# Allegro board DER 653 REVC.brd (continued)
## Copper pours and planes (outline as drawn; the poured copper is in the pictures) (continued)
PHASEW on TOP: 61.16,97.75 61.16,95.9 61.23,95.82 62.83,95.82 63.65,96.63 68.05,96.63 68.13,96.72 68.13,98.83 67.94,99.02 64.62,99.02 64.04,98.44 60.47,98.44 58.92,99.99 58.54,99.99 58.52,99.96 58.52,99.3 58.54,99.27 58.92,99.27 60.32,97.88 61.03,97.88
PHASEW on TOP: 58.97,99.25 53.18,99.25 53.08,99.35 53.08,103.16 51.23,105.02 48.66,105.02 48.23,105.45 48.23,109.5 48.25,109.51 48.25,110.09 49,110.84 70.23,110.84 70.74,110.33 70.74,105.84 70.51,105.61 60.48,105.61 58.97,104.1
PHASEW on BOTTOM: 48.39,99.5 48.39,113.29 48.92,113.83 80.1,113.83 81.26,112.67 81.26,102.76 79.62,101.13 71.87,101.13 70.13,99.39 70.12,99.39 69.85,99.12 48.77,99.12
SOURCE on TOP (solid shape): 27.1,17.05 23.8,17.05 23.8,21.88 27.1,21.88
SOURCE on TOP: 26.77,21.95 27.1,21.62 27.1,16.72 27.76,16.06 32.92,16.06 33.15,15.83 33.15,15.35 32.99,15.2 31.17,15.2 30.96,14.99 30.96,13.09 30.91,13.04 26.82,13.04 25.25,14.61 17.48,14.61 16.46,15.63 16.46,21.42 16.99,21.95
N11227943 on TOP: 25.06,83.46 22.61,83.46 22.61,84.71 24.3,84.71 25.76,86.17 25.76,90.51 25.65,90.61 25.65,91.04 25.68,91.07 26.64,91.07 26.92,90.79 26.92,85.33
N12134803 on TOP: 21.94,56.22 22.3,56.22 24.08,58 24.08,59.34 24.69,59.95 24.69,61.02 24.51,61.2 21.69,61.2 20.72,60.23 20.72,59.37 21.08,59.01 21.61,59.01 21.92,58.71 21.92,56.4 21.89,56.37 21.89,56.27
N12173083 on TOP: 22.12,74.06 22.12,73.53 22.25,73.4 27.25,73.4 27.43,73.58 27.43,74.44 27.38,74.5 23.95,74.5 23.62,74.16 22.22,74.16
N12173113 on TOP: 14.94,78.22 21.44,78.22 21.69,77.96 21.69,77.25 21.54,77.1 14.94,77.1 14.76,77.28 14.76,78.04
N12208110 on TOP: 51.31,22.16 44.93,22.16 44.37,21.6 44.37,18.65 45.31,17.71 50.83,17.71 51.97,18.86 51.97,21.5
N12208114 on TOP: 64.11,21.01 64.11,18.45 63.8,18.14 57.25,18.14 57.02,18.37 57.02,20.99 57.25,21.22 63.91,21.22

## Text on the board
Ref Des/Silkscreen Top: MOTOR DIRECTION | SWITCH | USB TO UART | AINB12 | SPEED CONTROL | 340VDC | CONNECTOR | JTAG/SWD | NRESET SWITCH | HIGH VOLTAGE | Phase_V | Phase_U | Phase_W | BPH_V | BPH_U | BPH_W | S/N | 1836 | DER-653 RevC
PAGE_OUTLINE: SLOTS
User.7: 14.  FAB HOUSE LOGO,DATE CODE TO BE IN SILK SCREEN ONLY.DO NOT USE COPPER. | 13.  MATERIAL FR4 COPPER 2oz THICKNESS 0.047"
User.9: FIGURE | FINISHED_SIZE | 12.0 | 20.0 | 27.559 | 30.0 | 30.984 | 36.0 | 40.0 | 60.0 | 110.0 | 156.0 | 74.803x27.559 | DRILL CHART: TOP to BOTTOM | ALL UNITS ARE IN MILS | PLATED | QTY | 55 | 511 | 5 | 4 | 2 | 20 | 31 | 8
